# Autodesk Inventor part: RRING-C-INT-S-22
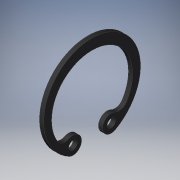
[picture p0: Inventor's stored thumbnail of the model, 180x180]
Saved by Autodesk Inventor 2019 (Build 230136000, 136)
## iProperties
Created: 2022-11
Part Number: RRING-C-INT-S-22
Material: Generic
Catalog Web Link: www.cadenas.de
Description: RRING_C_INT-Retaining Rings - C  (Internal)
Vendor: MISUMI
Document SubType Name: Modeling
Designer: psAdmin
Manufacturer: MISUMI
Mass: 0.128626 g
Surface Area: 3.94561 cm^2
Volume: 0.128626 cm^3
Density: 1 g/cm^3
Appearance: PSOLRGB-175-175-175
Category: PARTsolutions
Company: MISUMI
Title: RRING-C-INT-S-22
Author: Cadenas PARTsolutions
Comments: Retaining Rings - C  (Internal)
PSOL_IDENT_0: {$CADENAS_DATA/23d-libs/misumi/metric/accessories/rring_c_int.prj},181 {VTYP=3D},{NB=RRING-C-INT-S-2
PSOL_IDENT_1: 2},{LINA=RRING-C-INT-S-22},{NN=RRING_C_INT},{DATE=30.06.2021 13:30:10},{GEOMDATE=05.03.2015 00:00:00
PSOL_IDENT_2: },{VERSION=},{LINEID=120},{WBVAR=MAT},{WBNUMERIC=}  {NB=RRING-C-INT-S-22},{LINA=RRING-C-INT-S-22},{K
PSOL_IDENT_3: T=DUMMY},{PN=RRING-C-INT-S-22},{TYPE=RRING-C-INT},{MAT=-S},{HARD=36~44HRC},{NO=22},{DD3=23.5},{DD3TO
PSOL_IDENT_4: L=+0.2/-0.2},{TT=1.00},{TTTOL=+0.05/-0.05},{BB=2.5},{AA=4.1},{DD0=2.0},{DD4=13},{DD1=22},{DD2=23.0},
PSOL_IDENT_5: {DD2TOL=+0.21/0},{MM=1.15},{MMTOL=+0.14/0},{NN=1.5},{A2=9.10}
NB: RRING-C-INT-S-22
NN: 1.5
NT: Retaining Rings - C  (Internal)
NBSYN: $PN.
LINA: RRING-C-INT-S-22
CATALOG: Misumi
PN: RRING-C-INT-S-22
MAT: 304 Stainless Steel-CSP
HARD: 36~44HRC
NO: 22
DD3: 23.5
DD3TOL: +0.2/-0.2
TT: 1
TTTOL: +0.05/-0.05
BB: 2.5
AA: 4.1
DD0: 2
DD4: 13
DD1: 22
DD2: 23
DD2TOL: +0.21/0
MM: 1.15
MMTOL: +0.14/0
SUPPLIER: MISUMI
ARTICLENO: RRING-C-INT-S-22
BOMINFO: RRING-C-INT-S-22
CREATOR: CADENAS GmbH
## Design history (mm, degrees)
sketch "Sketch_3"
  geometry: L1 (-8.916, 2.599)-(-8.856, 2.582); L2 (-8.856, -2.582)-(-8.916, -2.599); C1 r 1 at (-8.283, -4.55); C2 r 1 at (-8.283, 4.55); A1 r 11.5 centre (0, 0) between (-10.115, -5.471) and (-10.115, 5.471); A2 r 2 centre (-8.356, 4.519) between (-10.115, 5.471) and (-8.916, 2.599); A3 r 2.05 centre (-8.283, 4.55) between (-8.856, 2.582) and (-6.46, 5.488); A4 r 2.05 centre (-4.637, 6.426) between (-5.722, 8.164) and (-6.46, 5.488); A5 r 9.625 centre (-0.625, 0) between (-5.722, -8.164) and (-5.722, 8.164); A6 r 2.05 centre (-4.637, -6.426) between (-6.46, -5.488) and (-5.722, -8.164); A7 r 2.05 centre (-8.283, -4.55) between (-6.46, -5.488) and (-8.856, -2.582); A8 r 2 centre (-8.356, -4.519) between (-8.916, -2.599) and (-10.115, -5.471); 2 further points
  constraints: 16 point on circle, 10 centre point, 4 end point
extrude "Extrusion1" join sketch "Sketch_3" stored distance "d0" = 1; taper "d1" = 0 deg
node "rr_XY"
node "rr_YZ"
node "rr_ZX"
node "rr_X"
node "rr_Y"
node "rr_Z"
node "rr_Center"
body "Solid1"
other parameters: "d2" = 0
